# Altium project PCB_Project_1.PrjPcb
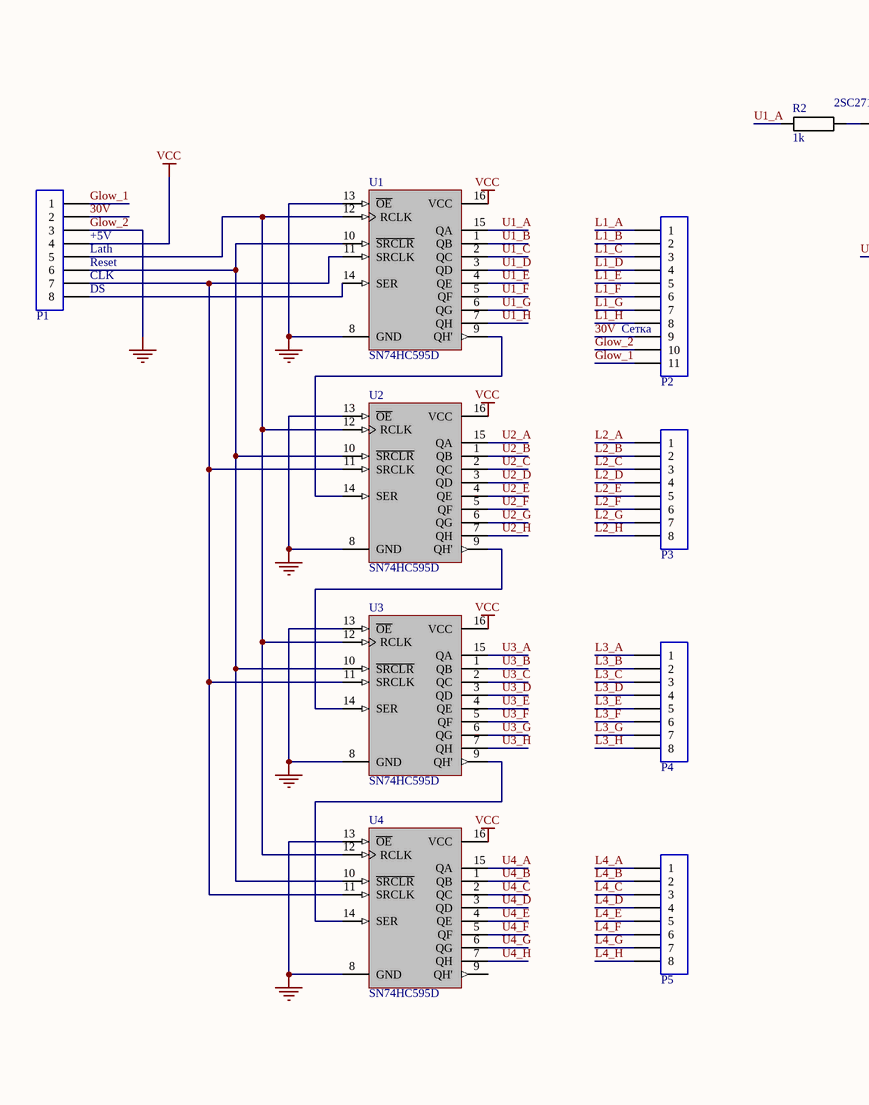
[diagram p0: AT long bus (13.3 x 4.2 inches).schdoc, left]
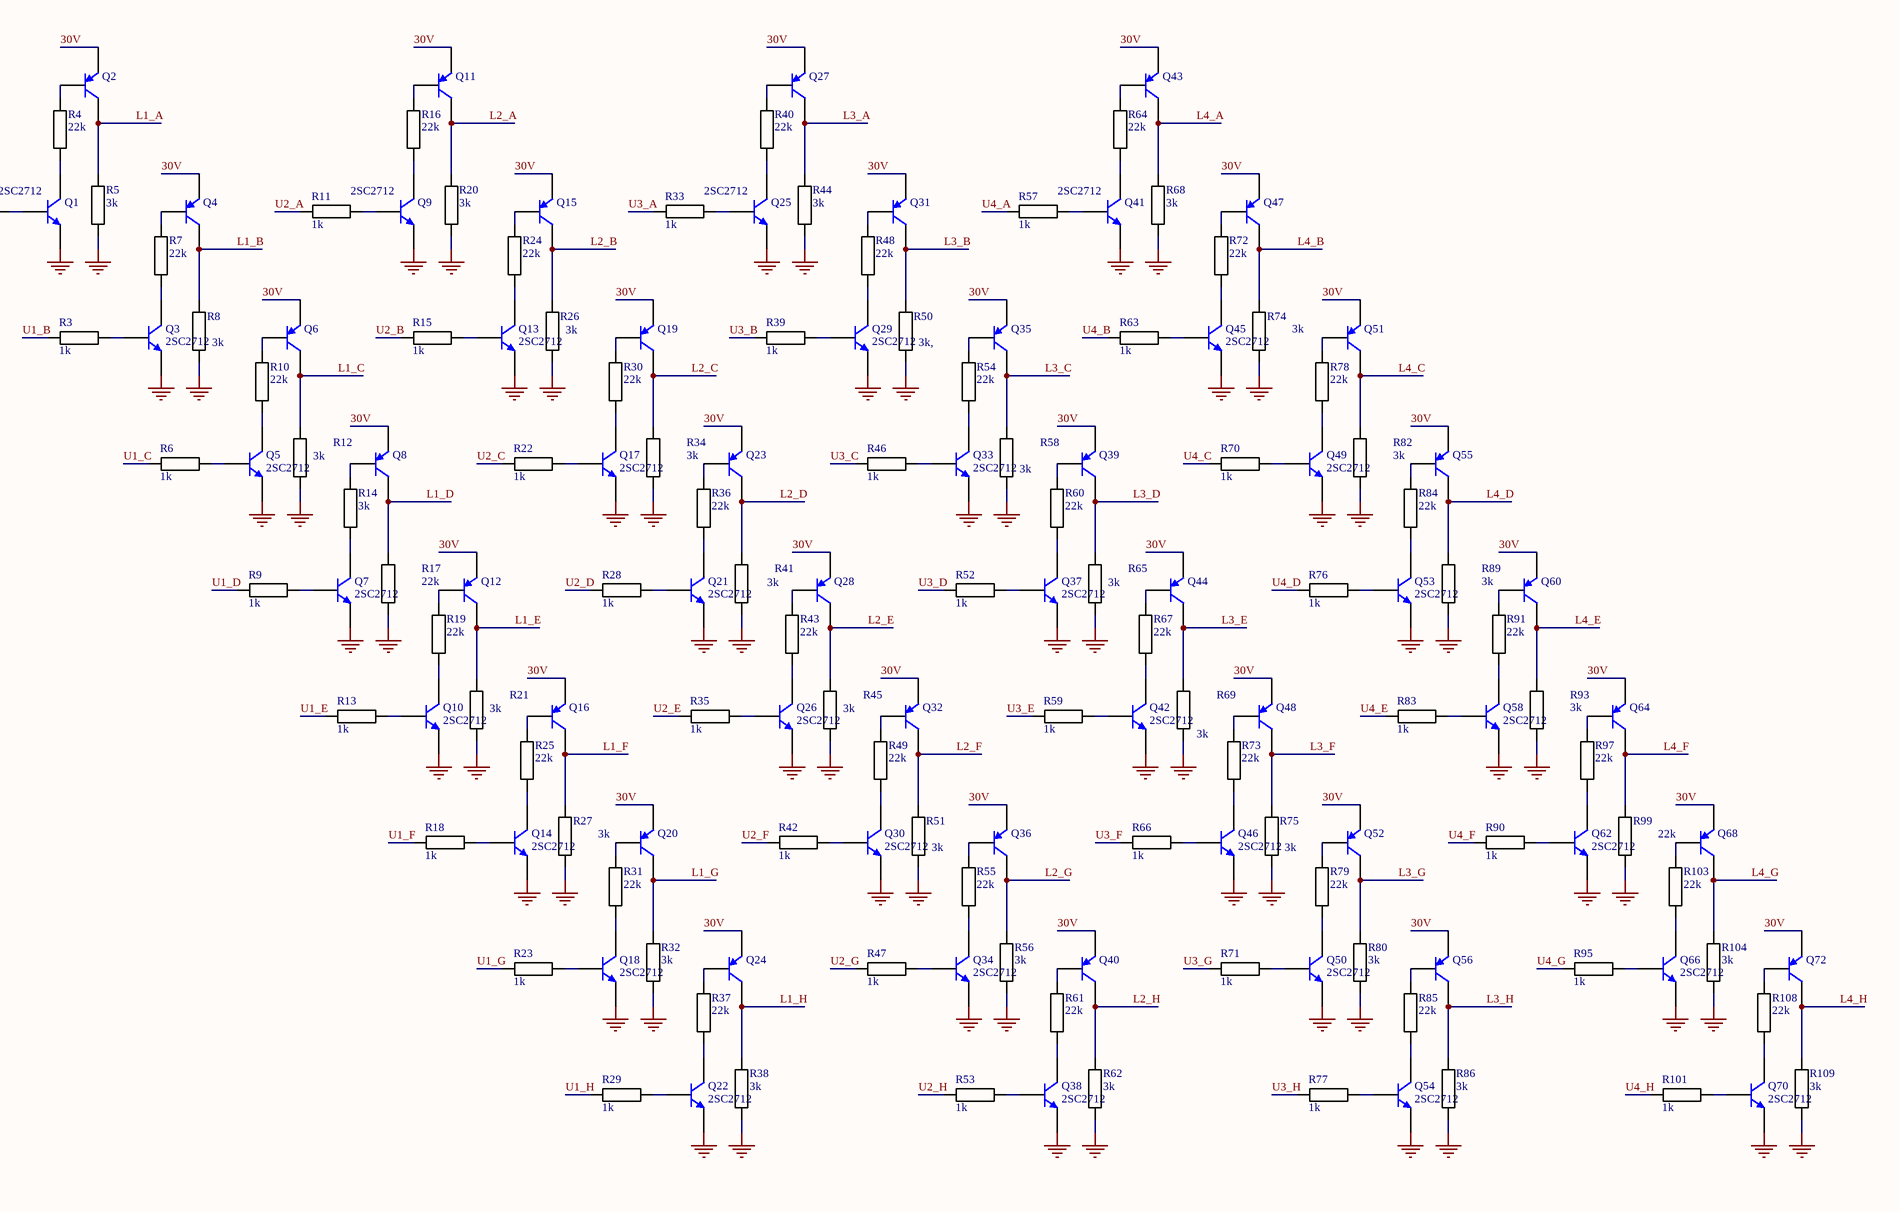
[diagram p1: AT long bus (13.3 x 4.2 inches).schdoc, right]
1 sheet, 169 parts. Net scope: global (net labels, ports and power ports of the same name join across sheets).
Board file: Ïÿòü ðàçðÿäîâ.PcbDoc

## Sheet AT long bus (13.3 x 4.2 inches).schdoc: AT long bus (13.3 x 4.2 inches)
size A1; Organization: Organization; Address1: Address1; Address2: Address2; Address3: Address3; Address4: Address4; DocumentNumber: 1; Revision: 0; SheetNumber: 2; SheetTotal: 2

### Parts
P1  Ещё порты  [HDR1X8]  (value not drawn)
P2  Ещё порты  [HDR_X11]  (value not drawn)
P3  Ещё порты  [HDR1X8]  (value not drawn)
P4  Ещё порты  [HDR1X8]  (value not drawn)
P5  Ещё порты  [HDR1X8]  (value not drawn)
Q1  2SC2712  [SOT23_N]
Q2  2SA1162  [SOT23_N]  (value not drawn)
Q3  2SC2712  [SOT23_N]
Q4  2SA1162  [SOT23_N]  (value not drawn)
Q5  2SC2712  [SOT23_N]
Q6  2SA1162  [SOT23_N]  (value not drawn)
Q7  2SC2712  [SOT23_N]
Q8  2SA1162  [SOT23_N]  (value not drawn)
Q9  2SC2712  [SOT23_N]
Q10  2SC2712  [SOT23_N]
Q11  2SA1162  [SOT23_N]  (value not drawn)
Q12  2SA1162  [SOT23_N]  (value not drawn)
Q13  2SC2712  [SOT23_N]
Q14  2SC2712  [SOT23_N]
Q15  2SA1162  [SOT23_N]  (value not drawn)
Q16  2SA1162  [SOT23_N]  (value not drawn)
Q17  2SC2712  [SOT23_N]
Q18  2SC2712  [SOT23_N]
Q19  2SA1162  [SOT23_N]  (value not drawn)
Q20  2SA1162  [SOT23_N]  (value not drawn)
Q21  2SC2712  [SOT23_N]
Q22  2SC2712  [SOT23_N]
Q23  2SA1162  [SOT23_N]  (value not drawn)
Q24  2SA1162  [SOT23_N]  (value not drawn)
Q25  2SC2712  [SOT23_N]
Q26  2SC2712  [SOT23_N]
Q27  2SA1162  [SOT23_N]  (value not drawn)
Q28  2SA1162  [SOT23_N]  (value not drawn)
Q29  2SC2712  [SOT23_N]
Q30  2SC2712  [SOT23_N]
Q31  2SA1162  [SOT23_N]  (value not drawn)
Q32  2SA1162  [SOT23_N]  (value not drawn)
Q33  2SC2712  [SOT23_N]
Q34  2SC2712  [SOT23_N]
Q35  2SA1162  [SOT23_N]  (value not drawn)
Q36  2SA1162  [SOT23_N]  (value not drawn)
Q37  2SC2712  [SOT23_N]
Q38  2SC2712  [SOT23_N]
Q39  2SA1162  [SOT23_N]  (value not drawn)
Q40  2SA1162  [SOT23_N]  (value not drawn)
Q41  2SC2712  [SOT23_N]
Q42  2SC2712  [SOT23_N]
Q43  2SA1162  [SOT23_N]  (value not drawn)
Q44  2SA1162  [SOT23_N]  (value not drawn)
Q45  2SC2712  [SOT23_N]
Q46  2SC2712  [SOT23_N]
Q47  2SA1162  [SOT23_N]  (value not drawn)
Q48  2SA1162  [SOT23_N]  (value not drawn)
Q49  2SC2712  [SOT23_N]
Q50  2SC2712  [SOT23_N]
Q51  2SA1162  [SOT23_N]  (value not drawn)
Q52  2SA1162  [SOT23_N]  (value not drawn)
Q53  2SC2712  [SOT23_N]
Q54  2SC2712  [SOT23_N]
Q55  2SA1162  [SOT23_N]  (value not drawn)
Q56  2SA1162  [SOT23_N]  (value not drawn)
Q58  2SC2712  [SOT23_N]
Q60  2SA1162  [SOT23_N]  (value not drawn)
Q62  2SC2712  [SOT23_N]
Q64  2SA1162  [SOT23_N]  (value not drawn)
Q66  2SC2712  [SOT23_N]
Q68  2SA1162  [SOT23_N]  (value not drawn)
Q70  2SC2712  [SOT23_N]
Q72  2SA1162  [SOT23_N]  (value not drawn)
R2  1k  [6-0805_N]
R3  1k  [6-0805_N]
R4  22k  [6-0805_N]
R5  3k  [6-0805_N]
R6  1k  [6-0805_N]
R7  22k  [6-0805_N]
R8  3k  [6-0805_N]
R9  1k  [6-0805_N]
R10  22k  [6-0805_N]
R11  1k  [6-0805_N]
R12  3k  [6-0805_N]
R13  1k  [6-0805_N]
R14  3k  [6-0805_N]
R15  1k  [6-0805_N]
R16  22k  [6-0805_N]
R17  22k  [6-0805_N]
R18  1k  [6-0805_N]
R19  22k  [6-0805_N]
R20  3k  [6-0805_N]
R21  3k  [6-0805_N]
R22  1k  [6-0805_N]
R23  1k  [6-0805_N]
R24  22k  [6-0805_N]
R25  22k  [6-0805_N]
R26  3k  [6-0805_N]
R27  3k  [6-0805_N]
R28  1k  [6-0805_N]
R29  1k  [6-0805_N]
R30  22k  [6-0805_N]
R31  22k  [6-0805_N]
R32  3k  [6-0805_N]
R33  1k  [6-0805_N]
R34  3k  [6-0805_N]
R35  1k  [6-0805_N]
R36  22k  [6-0805_N]
R37  22k  [6-0805_N]
R38  3k  [6-0805_N]
R39  1k  [6-0805_N]
R40  22k  [6-0805_N]
R41  3k  [6-0805_N]
R42  1k  [6-0805_N]
R43  22k  [6-0805_N]
R44  3k  [6-0805_N]
R45  3k  [6-0805_N]
R46  1k  [6-0805_N]
R47  1k  [6-0805_N]
R48  22k  [6-0805_N]
R49  22k  [6-0805_N]
R50  3k,  [6-0805_N]
R51  3k  [6-0805_N]
R52  1k  [6-0805_N]
R53  1k  [6-0805_N]
R54  22k  [6-0805_N]
R55  22k  [6-0805_N]
R56  3k  [6-0805_N]
R57  1k  [6-0805_N]
R58  3k  [6-0805_N]
R59  1k  [6-0805_N]
R60  22k  [6-0805_N]
R61  22k  [6-0805_N]
R62  3k  [6-0805_N]
R63  1k  [6-0805_N]
R64  22k  [6-0805_N]
R65  3k  [6-0805_N]
R66  1k  [6-0805_N]
R67  22k  [6-0805_N]
R68  3k  [6-0805_N]
R69  3k  [6-0805_N]
R70  1k  [6-0805_N]
R71  1k  [6-0805_N]
R72  22k  [6-0805_N]
R73  22k  [6-0805_N]
R74  3k  [6-0805_N]
R75  3k  [6-0805_N]
R76  1k  [6-0805_N]
R77  1k  [6-0805_N]
R78  22k  [6-0805_N]
R79  22k  [6-0805_N]
R80  3k  [6-0805_N]
R82  3k  [6-0805_N]
R83  1k  [6-0805_N]
R84  22k  [6-0805_N]
R85  22k  [6-0805_N]
R86  3k  [6-0805_N]
R89  3k  [6-0805_N]
R90  1k  [6-0805_N]
R91  22k  [6-0805_N]
R93  3k  [6-0805_N]
R95  1k  [6-0805_N]
R97  22k  [6-0805_N]
R99  22k  [6-0805_N]
R101  1k  [6-0805_N]
R103  22k  [6-0805_N]
R104  3k  [6-0805_N]
R108  22k  [6-0805_N]
R109  3k  [6-0805_N]
U1  SN74HC595D  [D016_N]
U2  SN74HC595D  [D016_N]
U3  SN74HC595D  [D016_N]
U4  SN74HC595D  [D016_N]

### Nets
Glow_2: P1.3 P2.10 Q1.2(E) Q3.2(E) Q5.2(E) Q7.2(E) Q9.2(E) Q10.2(E) Q13.2(E) Q14.2(E) Q17.2(E) Q18.2(E) Q21.2(E) Q22.2(E) Q25.2(E) Q26.2(E) Q29.2(E) Q30.2(E) Q33.2(E) Q34.2(E) Q37.2(E) Q38.2(E) Q41.2(E) Q42.2(E) Q45.2(E) Q46.2(E) Q49.2(E) Q50.2(E) Q53.2(E) Q54.2(E) Q58.2(E) Q62.2(E) Q66.2(E) Q70.2(E) R5.2 R8.2 R12.2 R17.2 R20.2 R21.2 R26.2 R27.2 R32.2 R34.2 R38.2 R41.2 R44.2 R45.2 R50.2 R51.2 R56.2 R58.2 R62.2 R65.2 R68.2 R69.2 R74.2 R75.2 R80.2 R82.2 R86.2 R89.2 R93.2 R99.2 R104.2 R109.2 U1.8(GND) U1.13(~{OE}) U2.8(GND) U2.13(~{OE}) U3.8(GND) U3.13(~{OE}) U4.8(GND) U4.13(~{OE})  [also labelled GND]
VCC: P1.4 U1.16(VCC) U2.16(VCC) U3.16(VCC) U4.16(VCC)
30V: P1.2 P2.9 Q2.2(E) Q4.2(E) Q6.2(E) Q8.2(E) Q11.2(E) Q12.2(E) Q15.2(E) Q16.2(E) Q19.2(E) Q20.2(E) Q23.2(E) Q24.2(E) Q27.2(E) Q28.2(E) Q31.2(E) Q32.2(E) Q35.2(E) Q36.2(E) Q39.2(E) Q40.2(E) Q43.2(E) Q44.2(E) Q47.2(E) Q48.2(E) Q51.2(E) Q52.2(E) Q55.2(E) Q56.2(E) Q60.2(E) Q64.2(E) Q68.2(E) Q72.2(E)
Glow_1: P1.1 P2.11
L1_A: P2.1 Q2.3(C) R5.1
L1_B: P2.2 Q4.3(C) R8.1
L1_C: P2.3 Q6.3(C) R12.1
L1_D: P2.4 Q8.3(C) R17.1
L1_E: P2.5 Q12.3(C) R21.1
L1_F: P2.6 Q16.3(C) R27.1
L1_G: P2.7 Q20.3(C) R32.1
L1_H: P2.8 Q24.3(C) R38.1
L2_A: P3.1 Q11.3(C) R20.1
L2_B: P3.2 Q15.3(C) R26.1
L2_C: P3.3 Q19.3(C) R34.1
L2_D: P3.4 Q23.3(C) R41.1
L2_E: P3.5 Q28.3(C) R45.1
L2_F: P3.6 Q32.3(C) R51.1
L2_G: P3.7 Q36.3(C) R56.1
L2_H: P3.8 Q40.3(C) R62.1
L3_A: P4.1 Q27.3(C) R44.1
L3_B: P4.2 Q31.3(C) R50.1
L3_C: P4.3 Q35.3(C) R58.1
L3_D: P4.4 Q39.3(C) R65.1
L3_E: P4.5 Q44.3(C) R69.1
L3_F: P4.6 Q48.3(C) R75.1
L3_G: P4.7 Q52.3(C) R80.1
L3_H: P4.8 Q56.3(C) R86.1
L4_A: P5.1 Q43.3(C) R68.1
L4_B: P5.2 Q47.3(C) R74.1
L4_C: P5.3 Q51.3(C) R82.1
L4_D: P5.4 Q55.3(C) R89.1
L4_E: P5.5 Q60.3(C) R93.1
L4_F: P5.6 Q64.3(C) R99.1
L4_G: P5.7 Q68.3(C) R104.1
L4_H: P5.8 Q72.3(C) R109.1
U1_A: R2.1 U1.15(QA)
U1_B: R3.1 U1.1(QB)
U1_C: R6.1 U1.2(QC)
U1_D: R9.1 U1.3(QD)
U1_E: R13.1 U1.4(QE)
U1_F: R18.1 U1.5(QF)
U1_G: R23.1 U1.6(QG)
U1_H: R29.1 U1.7(QH)
U2_A: R11.1 U2.15(QA)
U2_B: R15.1 U2.1(QB)
U2_C: R22.1 U2.2(QC)
U2_D: R28.1 U2.3(QD)
U2_E: R35.1 U2.4(QE)
U2_F: R42.1 U2.5(QF)
U2_G: R47.1 U2.6(QG)
U2_H: R53.1 U2.7(QH)
U3_A: R33.1 U3.15(QA)
U3_B: R39.1 U3.1(QB)
U3_C: R46.1 U3.2(QC)
U3_D: R52.1 U3.3(QD)
U3_E: R59.1 U3.4(QE)
U3_F: R66.1 U3.5(QF)
U3_G: R71.1 U3.6(QG)
U3_H: R77.1 U3.7(QH)
U4_A: R57.1 U4.15(QA)
U4_B: R63.1 U4.1(QB)
U4_C: R70.1 U4.2(QC)
U4_D: R76.1 U4.3(QD)
U4_E: R83.1 U4.4(QE)
U4_F: R90.1 U4.5(QF)
U4_G: R95.1 U4.6(QG)
U4_H: R101.1 U4.7(QH)
NetP1_5: P1.5 U1.12(RCLK) U2.12(RCLK) U3.12(RCLK) U4.12(RCLK)
NetP1_6: P1.6 U1.10(~{SRCLR}) U2.10(~{SRCLR}) U3.10(~{SRCLR}) U4.10(~{SRCLR})
NetP1_7: P1.7 U1.11(SRCLK) U2.11(SRCLK) U3.11(SRCLK) U4.11(SRCLK)
NetP1_8: P1.8 U1.14(SER)
NetQ1_1: Q1.1(B) R2.2
NetQ1_3: Q1.3(C) R4.2
NetQ2_1: Q2.1(B) R4.1
NetQ3_1: Q3.1(B) R3.2
NetQ3_3: Q3.3(C) R7.2
NetQ4_1: Q4.1(B) R7.1
NetQ5_1: Q5.1(B) R6.2
NetQ5_3: Q5.3(C) R10.2
NetQ6_1: Q6.1(B) R10.1
NetQ7_1: Q7.1(B) R9.2
NetQ7_3: Q7.3(C) R14.2
NetQ8_1: Q8.1(B) R14.1
NetQ9_1: Q9.1(B) R11.2
NetQ9_3: Q9.3(C) R16.2
NetQ10_1: Q10.1(B) R13.2
NetQ10_3: Q10.3(C) R19.2
NetQ11_1: Q11.1(B) R16.1
NetQ12_1: Q12.1(B) R19.1
NetQ13_1: Q13.1(B) R15.2
NetQ13_3: Q13.3(C) R24.2
NetQ14_1: Q14.1(B) R18.2
NetQ14_3: Q14.3(C) R25.2
NetQ15_1: Q15.1(B) R24.1
NetQ16_1: Q16.1(B) R25.1
NetQ17_1: Q17.1(B) R22.2
NetQ17_3: Q17.3(C) R30.2
NetQ18_1: Q18.1(B) R23.2
NetQ18_3: Q18.3(C) R31.2
NetQ19_1: Q19.1(B) R30.1
NetQ20_1: Q20.1(B) R31.1
NetQ21_1: Q21.1(B) R28.2
NetQ21_3: Q21.3(C) R36.2
NetQ22_1: Q22.1(B) R29.2
NetQ22_3: Q22.3(C) R37.2
NetQ23_1: Q23.1(B) R36.1
NetQ24_1: Q24.1(B) R37.1
NetQ25_1: Q25.1(B) R33.2
NetQ25_3: Q25.3(C) R40.2
NetQ26_1: Q26.1(B) R35.2
NetQ26_3: Q26.3(C) R43.2
NetQ27_1: Q27.1(B) R40.1
NetQ28_1: Q28.1(B) R43.1
NetQ29_1: Q29.1(B) R39.2
NetQ29_3: Q29.3(C) R48.2
NetQ30_1: Q30.1(B) R42.2
NetQ30_3: Q30.3(C) R49.2
NetQ31_1: Q31.1(B) R48.1
NetQ32_1: Q32.1(B) R49.1
NetQ33_1: Q33.1(B) R46.2
NetQ33_3: Q33.3(C) R54.2
NetQ34_1: Q34.1(B) R47.2
NetQ34_3: Q34.3(C) R55.2
NetQ35_1: Q35.1(B) R54.1
NetQ36_1: Q36.1(B) R55.1
NetQ37_1: Q37.1(B) R52.2
NetQ37_3: Q37.3(C) R60.2
NetQ38_1: Q38.1(B) R53.2
NetQ38_3: Q38.3(C) R61.2
NetQ39_1: Q39.1(B) R60.1
NetQ40_1: Q40.1(B) R61.1
NetQ41_1: Q41.1(B) R57.2
NetQ41_3: Q41.3(C) R64.2
NetQ42_1: Q42.1(B) R59.2
NetQ42_3: Q42.3(C) R67.2
NetQ43_1: Q43.1(B) R64.1
NetQ44_1: Q44.1(B) R67.1
NetQ45_1: Q45.1(B) R63.2
NetQ45_3: Q45.3(C) R72.2
NetQ46_1: Q46.1(B) R66.2
NetQ46_3: Q46.3(C) R73.2
NetQ47_1: Q47.1(B) R72.1
NetQ48_1: Q48.1(B) R73.1
NetQ49_1: Q49.1(B) R70.2
NetQ49_3: Q49.3(C) R78.2
NetQ50_1: Q50.1(B) R71.2
NetQ50_3: Q50.3(C) R79.2
NetQ51_1: Q51.1(B) R78.1
NetQ52_1: Q52.1(B) R79.1
NetQ53_1: Q53.1(B) R76.2
NetQ53_3: Q53.3(C) R84.2
NetQ54_1: Q54.1(B) R77.2
NetQ54_3: Q54.3(C) R85.2
NetQ55_1: Q55.1(B) R84.1
NetQ56_1: Q56.1(B) R85.1
NetQ58_1: Q58.1(B) R83.2
NetQ58_3: Q58.3(C) R91.2
NetQ60_1: Q60.1(B) R91.1
NetQ62_1: Q62.1(B) R90.2
NetQ62_3: Q62.3(C) R97.2
NetQ64_1: Q64.1(B) R97.1
NetQ66_1: Q66.1(B) R95.2
NetQ66_3: Q66.3(C) R103.2
NetQ68_1: Q68.1(B) R103.1
NetQ70_1: Q70.1(B) R101.2
NetQ70_3: Q70.3(C) R108.2
NetQ72_1: Q72.1(B) R108.1
NetU1_9: U1.9(QH') U2.14(SER)
NetU2_9: U2.9(QH') U3.14(SER)
NetU3_9: U3.9(QH') U4.14(SER)

Not connected (* = marked no-connect by the designer): U4 9(QH')

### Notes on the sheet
- (near P1) Lath
- (near P1) Reset
- (near P1) CLK
- (near P1) +5V
- (near P1) DS
- (near P2) Сетка

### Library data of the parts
P1 P3-P5 = Header 9: Header, 9-Pin
P2 = Header 11: Header, 11-Pin
Q1 Q3 Q5 Q7 Q9 Q10 Q13 Q14 Q17 Q18 Q21 Q22 Q25 Q26 Q29 Q30 Q33 Q34 Q37 Q38 Q41 Q42 Q45 Q46 Q49 Q50 Q53 Q54 Q58 Q62 Q66 Q70 = 2SC2712: NPN
Q2 Q4 Q6 Q8 Q11 Q12 Q15 Q16 Q19 Q20 Q23 Q24 Q27 Q28 Q31 Q32 Q35 Q36 Q39 Q40 Q43 Q44 Q47 Q48 Q51 Q52 Q55 Q56 Q60 Q64 Q68 Q72 = 2SA1162: PNP
R5 R8 R12 R14 R20 R21 R26 R27 R32 R34 R38 R41 R44 R45 R50 R51 R56 R58 R62 R65 R68 R69 R74 R75 R80 R82 R86 R89 R93 R104 R109 = 22k
U1-U4 = SN74HC595D: 8-Bit Shift Register with 3-State Output Registers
